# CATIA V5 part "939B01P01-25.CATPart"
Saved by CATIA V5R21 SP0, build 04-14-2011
Part number: 939B01P01-25
Bounding box of the stored display mesh (mm): x -17.1 to 17.1, y -76.2 to 76.2, z -4.4 to 20.6
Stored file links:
  C:\Users\ALI OZGUN\Desktop\alhan\TESLIMEDILEN3\939B01P01-25.CATPart
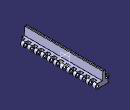
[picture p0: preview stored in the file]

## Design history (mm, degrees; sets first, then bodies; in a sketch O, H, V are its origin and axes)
Body1 (main body)
  Sketch1 on zx-plane, origin (0, 0, 0), H (-1, 0, 0), V (0, 0, 1)
    construction line L1 (-12.7, 0) -> (12.7, 0)
    point P1 (-12.7, 0)
    line L2 (-12.7, 4.4) -> (12.7, 4.4)
    line L3 (12.7, -4.4) -> (-12.7, -4.4)
    arc A1 centre (12.7, 0) radius 4.4 from (12.7, 4.4) to (12.7, -4.4) cw
    arc A2 centre (-12.7, 0) radius 4.4 from (-12.7, -4.4) to (-12.7, 4.4) cw
    distance L1 L2 = 4.4
    length L1 = 25.4
    distance P1 V = 12.7
    coincidence: P1 H
    horizontal: L1 H
    tangency: A1 L2, A2 L2, A1 L3, A2 L3
  Pad1: profile Sketch1, direction (0, 1, 0), length 76.2, mirrored extent
  Sketch2 on face of Pad1 from Sketch1.L2, origin (0, 0, 4.4), H (1, 0, 0), V (0, 1, 0)
    line L1 (-22.3127, -63.5) -> (-9.75, -63.5)
    line L2 (-9.75, -63.5) -> (-9.75, -70.6)
    line L3 (-9.75, -70.6) -> (-22.3127, -70.6)
    line L4 (-22.3127, -70.6) -> (-22.3127, -63.5)
    line L5 (24.6678, -76.95) -> (9.75, -76.95)
    line L6 (9.75, -76.95) -> (9.75, -69.85)
    line L7 (9.75, -69.85) -> (24.6678, -69.85)
    line L8 (24.6678, -69.85) -> (24.6678, -76.95)
    reference projected line E1 (-12.7, -76.2) -> (12.7, -76.2) from edge [start face of Pad1 | face of Pad1 from Sketch1.L2]
    reference projected line E2 (-12.7, -76.2) -> (12.7, -76.2) from edge [start face of Pad1 | face of Pad1 from Sketch1.L2]
    distance L3 E1 = 5.6
    length L4 = 7.1
    distance L7 L5 = 7.1
    distance L5 E2 = 0.75
    distance L2 L6 = 19.5
    distance L2 V = 9.75
    horizontal: L1 H, L3 H, L5 H, L7 H
    vertical: L2 V, L4 V, L6 V, L8 V
  Pocket1: profile Sketch2, direction (0, 0, -1), length 76.2
  RectPattern1: of Pocket1, direction 1 instances 12, spacing 12.7, along axis of face of Pad1 from Sketch1.A2
  Sketch3 on face of Pad1 from Sketch1.L3, origin (0, 0, -4.4), H (1, 0, 0), V (0, -1, 0)
    line L1 (-6.5, -54.6) -> (6.5, -54.6)
    line L2 (6.5, -54.6) -> (6.5, -73.7)
    line L3 (6.5, -73.7) -> (-6.5, -73.7)
    line L4 (-6.5, -73.7) -> (-6.5, -54.6)
    construction line L5 (-4.5, -51.1) -> (4.5, -51.1)
    point P5 (-4.5, -51.1)
    line L6 (-4.5, -49.6) -> (4.5, -49.6)
    line L7 (4.5, -52.6) -> (-4.5, -52.6)
    arc A1 centre (4.5, -51.1) radius 1.5 from (4.5, -49.6) to (4.5, -52.6) cw
    arc A2 centre (-4.5, -51.1) radius 1.5 from (-4.5, -52.6) to (-4.5, -49.6) cw
    reference projected line E1 (12.7, -76.2) -> (-12.7, -76.2) from edge [face of Pad1 from Sketch1.L3 | end face of Pad1]
    distance L5 L6 = 1.5
    distance L1 L3 = 19.1
    distance L4 L2 = 13
    distance L4 V = 6.5
    distance E1 L3 = 2.5
    distance P5 V = 4.5
    length L5 = 9
    distance L7 L1 = 2
    horizontal: L1 H, L3 H, L5 H
    vertical: L2 V, L4 V
    tangency: A1 L6, A2 L6, A1 L7, A2 L7
  Pocket2: profile Sketch3, direction (0, 0, 1), length 6
  RectPattern2: of Pocket2, direction 1 instances 6, spacing 25.8, along axis of face of Pad1 from Sketch1.A2 reversed
  Sketch4 on zx-plane, origin (0, 0, 0), H (-1, 0, 0), V (0, 0, 1)
    circle A1 centre (12.7, 0) radius 2.3
    point P1 (12.7, 0)
    circle A2 centre (-12.7, 0) radius 2.3
    point P2 (-12.7, 0)
    reference projected arc E1 centre (12.7, 0) radius 4.4 from (12.7, -4.4) to (12.7, 4.4) ccw from edge [face of RectPattern1 | face of Pad1 from Sketch1.A1]
    reference projected arc E2 centre (-12.7, 0) radius 4.4 from (-12.7, 4.4) to (-12.7, -4.4) ccw from edge [face of Pad1 from Sketch1.A2 | end face of Pad1]
    radius A1 = 2.3
    radius A2 = 2.3
    coincidence: P1 H, P2 H
    concentricity: P1 E1, A2 E2
  Pocket3: profile Sketch4, direction (0, -1, 0), length 97.8, mirrored extent
  Body2
    Solid1: linked copy from another document
    Symmetry1: Reference yz-plane, ToTransfor Solid1
    Translate1: Direction edge [face of Pocket1 from Sketch2.L2 | face of Pad1 from Sketch1.L3], Length 6.35, ToTransfor Symmetry1
    Body3
      Sketch5 on face of RectPattern1, origin (9.75, 0, 0), H (0, 1, 0), V (0, 0, 1)
      Pad2: profile Sketch5, direction (1, 0, 0), length 12
      Sketch6 on face of Pad2, origin (0, 69.85, 0), H (-1, 0, 0), V (0, 0, 1)
        point P2 (-21.75, 4.4)
        arc A1 centre (-16.4898, 1.5645) radius 9 from (-9.75, -4.4) to (-7.9481, 4.4) ccw
        point P8 (-21.75, 4.4)
        construction line L1 (-9.75, 4.4) -> (-21.75, 4.4)
        line L2 (-7.9481, 4.4) -> (-21.75, 4.4)
        line L3 (-9.75, -4.4) -> (-21.75, -4.4)
        line L4 (-21.75, -4.4) -> (-21.75, 4.4)
        radius A1 = 9
        coincidence: P2 P8
      Pad3: profile Sketch6, direction (0, 1, 0), up to face of Pad2
      RectPattern3: of the body so far, direction 1 instances 12, spacing 12.7, along edge [face of Pad3 | face of Pad3] reversed
    Add1: tool Body3
  Remove1: tool Body2
  Sketch7 on zx-plane, origin (0, 0, 0), H (-1, 0, 0), V (0, 0, 1)
    projected line E1 (7.9481, 4.4) -> (-12.7, 4.4) from edge [face of Pad1 from Sketch1.L2 | end face of Pad1]
    projected line E2 (3.2, 4.4) -> (-3.2, 4.4) from edge [face of Pad1 from Sketch1.L2 | end face of Pad1]
    point P3 (-3.2, 4.4)
    line L1 (-3.2, 4.4) -> (-2, 20.6)
    point P4 (-2, 20.6)
    line L2 (-2, 20.6) -> (2, 20.6)
    line L3 (2, 20.6) -> (3.2, 4.4)
    reference projected line E3 (-12.7, -4.4) -> (12.7, -4.4) from edge [face of Pad1 from Sketch1.L3 | end face of Pad1]
    distance L2 E3 = 25
    distance P3 V = 3.2
    distance P4 V = 2
    coincidence: P3 E1, P3 L1
    horizontal: L2 H
    symmetry: L1 L3 V
  Pad4: profile Sketch7, direction (0, 1, 0), length 76.2, mirrored extent
  Fillet1: radius 1, on edge [face of Pad4 from Sketch7.L2 | face of Pad4 from Sketch7.L3]; edge [face of Pad4 from Sketch7.L1 | face of Pad4 from Sketch7.L2]
Body4
  Solid2: linked copy from another document
  Translate2: Direction yz-plane, Length 25.4, ToTransfor Solid2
